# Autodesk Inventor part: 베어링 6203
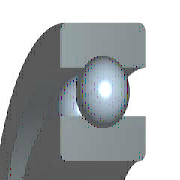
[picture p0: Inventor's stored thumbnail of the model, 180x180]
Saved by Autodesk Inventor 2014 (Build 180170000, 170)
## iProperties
IsCustomPart: 1
Created: 2015-09
Part Number: 베어링 6203
Material: 강철, 연강
Description: 깊은 그루브 볼 베어링
Document SubType Name: Modeling
Standard: KS B 2023
Standards Organization: KS
Language: ko-KR
Size Designation: 6203 - 17 x 40 x 12
Categories: <MemberInstance><Categories><Category DisplayName="샤프트 부품" InternalName="7f7aeb1f-a693-4053-b835-cee3144e0d98" Mnemonic="SHFT"><Category DisplayName="베어링" Inter
Density: 7.86 g/cm^3
Mass: 58.8203 g
Surface Area: 64.3582 cm^2
Volume: 7.4835 cm^3
Appearance: Steel
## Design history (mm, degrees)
sketch "스케치" dims "d0" = 5.98 (= -0.26 x WD + 0.26 x BD)
  geometry: L1 (3.01, 14.25)-(8.99, 14.25); L2 (6, 14.25)-(6, 11.26); L3 (6, 14.25)-(6, 17.24); L4 (3.778, 12.249)-(0, 12.249); L5 (0, 8.5)-(12, 8.5); L6 (3.778, 16.251)-(0, 16.251); L7 (0, 20)-(12, 20); L8 (12, 8.5)-(12, 12.249); L9 (8.222, 12.249)-(12, 12.249); L10 (8.222, 16.251)-(12, 16.251); L11 (12, 20)-(12, 16.251); L12 (-1.4, 0)-(8.4, 0) reference; L13 (0, -0.3)-(0, 5.3) reference
  constraints: 22 end point, 4 point on line, 2 collinear, 2 perpendicular, 2 symmetric about line, 1 midpoint, 1 parallel, 14 other
  dimensions: "d9" = 17 diameter of L5 L12 (= WD); "d11" = 40 diameter of L7 L12 (= BD); "d12" = 12 distance between parallel lines of L8 L13 (= KB); "d13" = 24.498 diameter of L9 L12 (= 0.326 x BD + 0.674 x WD)
revolve "본체" stored, may be unused: angle "d6" = 90 deg
revolve "볼" stored, may be unused: angle "d7" = 90 deg
pattern_circular "IDS_ARRAYBALL[SIMPL:T]" dims angle "d3" = 360 deg
body "Solid1"
fillet "모깎기1" dims "d1" = 0.6 (= KRS)
other parameters: "WD" = 17 [user parameter; used in 5 equation terms], "BD" = 40 [user parameter; used in 5 equation terms], "KB" = 12 [user parameter; used in 1 equation term], "KRS" = 0.6 [user parameter; used in 1 equation term], "d4" = 0, "d5" = 0, "d8" = 0, "d14" = 0, "d15" = 0, "BBA" = 0 [user parameter], "BC0" = 4750000 [user parameter], "BC" = 9560000 [user parameter], "WR" = 8.5 (= 0.5 x WD) [user parameter]
